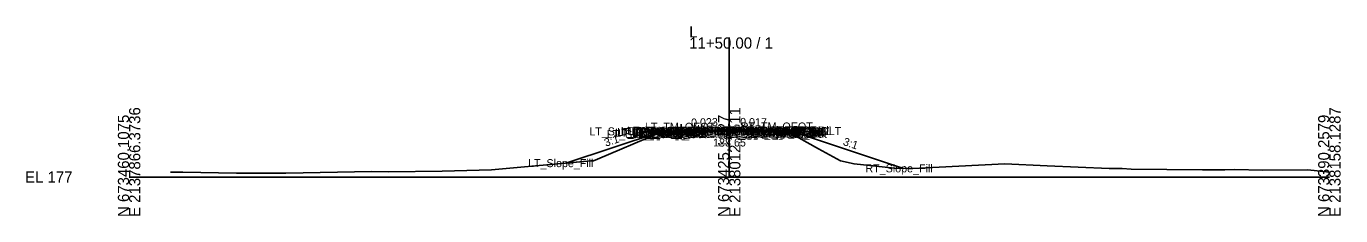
# Model space of a CAD drawing. Extents: x -26 to 5503, y -10 to 7033.
# Drawn here: x -25.7 to 302.8, y 2490.3 to 2537.8 of the extents above; entities that cross this region are included whole.
import ezdxf

# ---------------------------------------------------------------- set-up
doc = ezdxf.new("R2010")
doc.units = 0
for name, color, linetype in [('Default', 7, 'Continuous'), ('Exist CMT Pavement', 7, 'Continuous'), ('Exist Cross Section Cell', 7, 'Continuous'), ('Exist XS Center Line Elevation Label', 7, 'Continuous'), ('Exist XS Ground Line', 7, 'Continuous'), ('Prop CMT Pvmt Course 1', 7, 'Continuous'), ('Prop CMT Pvmt Course 1 Wedge', 7, 'Continuous'), ('Prop CMT Pvmt Course 2', 7, 'Continuous'), ('Prop CMT Pvmt Course 2 Wedge', 7, 'Continuous'), ('Prop CMT Pvmt Course 3', 7, 'Continuous'), ('Prop CMT Pvmt Course 3 Wedge', 7, 'Continuous'), ('Prop CMT Pvmt Surface', 7, 'Continuous'), ('Prop CMT Pvmt Surface Shoulder', 7, 'Continuous'), ('Prop CMT Pvmt Wedge Surface 1', 7, 'Continuous'), ('Prop CMT Pvmt Wedge Surface 2', 7, 'Continuous'), ('Prop CMT Pvmt Wedge Surface 3', 7, 'Continuous'), ('Prop CMT Shld Paved Course 1', 7, 'Continuous'), ('Prop CMT Shld Paved Course 2', 7, 'Continuous'), ('Prop CMT Shld Paved Course 3', 7, 'Continuous'), ('Prop CMT Slope Grass', 7, 'Continuous'), ('Prop CMT Subgrade Earthwork', 7, 'Continuous'), ('Prop XS Earthwork Shape', 7, 'Continuous'), ('Prop XS EOT Tick Mark', 7, 'Continuous'), ('Prop XS SE Text', 7, 'Continuous'), ('Prop XS Side Slope Text', 7, 'Continuous'), ('Prop XS Wedging', 7, 'Continuous')]:
    doc.layers.add(name, color=color, linetype=linetype)

msp = doc.modelspace()

# ---------------------------------------------------------------- linework, layer by layer
at = {"layer": 'Exist CMT Pavement'}
for points in [[(150, 2511.65), (148.67, 2511.63), (144, 2511.57), (139.33, 2511.51), (138, 2511.48)], [(150, 2511.65), (151.32, 2511.63), (155.94, 2511.52), (160.55, 2511.4), (161.87, 2511.36)]]:
    msp.add_lwpolyline(points, dxfattribs=at)
at = {"layer": 'Exist Cross Section Cell'}
for p, q in [((150, 2500), (150, 2534.96)), ((0, 2500), (150, 2500)), ((150, 2500), (300, 2500))]:
    msp.add_line(p, q, dxfattribs=at)
at = {"layer": 'Exist XS Ground Line'}
for p, q in [((117.07, 2504.49), (131.96, 2510.78)), ((131.96, 2510.78), (134.68, 2511.04)), ((134.68, 2511.04), (137.79, 2511.48)), ((137.79, 2511.48), (141.28, 2511.54)), ((141.28, 2511.54), (150.19, 2511.65)), ((150.19, 2511.65), (153.64, 2511.58)), ((153.64, 2511.58), (161.85, 2511.36)), ((161.85, 2511.36), (163.29, 2511.22)), ((163.29, 2511.22), (165.34, 2511.03)), ((165.34, 2511.03), (172.31, 2507.1)), ((172.31, 2507.1), (177.84, 2504.04)), ((90.58, 2501.84), (115.38, 2504.02)), ((115.38, 2504.02), (116.06, 2504.06)), ((116.06, 2504.06), (117.07, 2504.49)), ((177.84, 2504.04), (181.23, 2503.29)), ((10.32, 2501.22), (13.46, 2501.23)), ((13.46, 2501.23), (26.87, 2501.01)), ((26.87, 2501.01), (39.17, 2500.97)), ((39.17, 2500.97), (60.67, 2501.35)), ((60.67, 2501.35), (64.88, 2501.33)), ((64.88, 2501.33), (78.25, 2501.5)), ((78.25, 2501.5), (90.58, 2501.84)), ((181.23, 2503.29), (191.32, 2502.24)), ((191.32, 2502.24), (195.86, 2502.11)), ((195.86, 2502.11), (218.89, 2503.34)), ((218.89, 2503.34), (229.46, 2502.81)), ((229.46, 2502.81), (245, 2502.15)), ((245, 2502.15), (246.8, 2502.16)), ((246.8, 2502.16), (248.2, 2502.14)), ((248.2, 2502.14), (250.48, 2502)), ((250.48, 2502), (268.33, 2501.81)), ((268.33, 2501.81), (270.6, 2501.8)), ((270.6, 2501.8), (272.18, 2501.81)), ((272.18, 2501.81), (273.91, 2501.82)), ((273.91, 2501.82), (276.4, 2501.85)), ((276.4, 2501.85), (283.27, 2501.76)), ((283.27, 2501.76), (294.6, 2501.77)), ((294.6, 2501.77), (300, 2501.24))]:
    msp.add_line(p, q, dxfattribs=at)
at = {"layer": 'Prop CMT Pvmt Course 1'}
for points in [[(150, 2511.87), (138, 2511.59)], [(138, 2511.47), (150, 2511.74)], [(138, 2511.59), (138, 2511.34), (138, 2511.34), (138, 2511.47)], [(150, 2511.74), (150, 2511.87)], [(150, 2511.87), (162, 2511.66)], [(150, 2511.74), (150, 2511.87)], [(161.87, 2511.53), (150, 2511.74)], [(161.87, 2511.41), (161.87, 2511.53)], [(162, 2511.41), (161.87, 2511.41)], [(162, 2511.66), (162, 2511.41)]]:
    msp.add_lwpolyline(points, dxfattribs=at)
at = {"layer": 'Prop CMT Pvmt Course 1 Wedge'}
for points in [[(150, 2511.74), (138, 2511.47)], [(150, 2511.74), (161.87, 2511.53)]]:
    msp.add_lwpolyline(points, dxfattribs=at)
at = {"layer": 'Prop CMT Pvmt Course 2'}
for points in [[(161.87, 2511.2), (161.87, 2511.41)], [(161.87, 2511.41), (162, 2511.41)], [(162, 2511.2), (161.87, 2511.2)], [(162, 2511.41), (162, 2511.2)]]:
    msp.add_lwpolyline(points, dxfattribs=at)
at = {"layer": 'Prop CMT Pvmt Course 2 Wedge'}
for points in [[(150, 2511.62), (138, 2511.34)], [(150, 2511.62), (161.87, 2511.41)]]:
    msp.add_lwpolyline(points, dxfattribs=at)
at = {"layer": 'Prop CMT Pvmt Course 3'}
for points in [[(138, 2511.14), (138, 2511.14), (138, 2510.8), (138, 2510.8)], [(138, 2510.8), (138, 2511.14)], [(161.87, 2511.2), (162, 2511.2)], [(161.87, 2510.87), (161.87, 2511.2)], [(162, 2510.87), (161.87, 2510.87)], [(162, 2511.2), (162, 2510.87)]]:
    msp.add_lwpolyline(points, dxfattribs=at)
at = {"layer": 'Prop CMT Pvmt Course 3 Wedge'}
for points in [[(150, 2511.41), (138, 2511.14)], [(150, 2511.41), (161.87, 2511.2)]]:
    msp.add_lwpolyline(points, dxfattribs=at)
at = {"layer": 'Prop CMT Pvmt Surface'}
for points in [[(150, 2511.87), (138, 2511.59)], [(150, 2511.87), (162, 2511.66)]]:
    msp.add_lwpolyline(points, dxfattribs=at)
at = {"layer": 'Prop CMT Pvmt Surface Shoulder'}
for points in [[(138, 2511.59), (135.96, 2511.55)], [(162, 2511.66), (164.02, 2511.62)]]:
    msp.add_lwpolyline(points, dxfattribs=at)
at = {"layer": 'Prop CMT Pvmt Wedge Surface 1'}
for points in [[(150, 2511.74), (138, 2511.47)], [(138, 2511.47), (138, 2511.59)], [(138, 2511.59), (138, 2511.59)], [(150, 2511.74), (161.87, 2511.53)], [(161.87, 2511.53), (161.87, 2511.66)], [(161.87, 2511.66), (162, 2511.66)]]:
    msp.add_lwpolyline(points, dxfattribs=at)
at = {"layer": 'Prop CMT Pvmt Wedge Surface 2'}
for points in [[(150, 2511.62), (138, 2511.34)], [(138, 2511.34), (138, 2511.59)], [(138, 2511.34), (138, 2511.34)], [(150, 2511.62), (161.87, 2511.41), (162, 2511.41)], [(162, 2511.41), (162, 2511.66)]]:
    msp.add_lwpolyline(points, dxfattribs=at)
at = {"layer": 'Prop CMT Pvmt Wedge Surface 3'}
for points in [[(138, 2511.14), (138, 2511.59)], [(150, 2511.41), (138, 2511.14)], [(138, 2511.14), (138, 2511.14)], [(150, 2511.41), (161.87, 2511.2), (162, 2511.2)], [(162, 2511.2), (162, 2511.66)]]:
    msp.add_lwpolyline(points, dxfattribs=at)
at = {"layer": 'Prop CMT Shld Paved Course 1'}
for points in [[(138, 2511.59), (135.96, 2511.55), (135.71, 2511.29)], [(135.71, 2511.29), (138, 2511.34)], [(138, 2511.34), (138, 2511.59)], [(162, 2511.66), (164.02, 2511.62), (164.28, 2511.37)], [(162, 2511.41), (162, 2511.66)], [(164.28, 2511.37), (162, 2511.41)]]:
    msp.add_lwpolyline(points, dxfattribs=at)
at = {"layer": 'Prop CMT Shld Paved Course 2'}
for points in [[(138, 2511.34), (135.71, 2511.29), (135.49, 2511.08)], [(135.49, 2511.08), (138, 2511.14)], [(138, 2511.14), (138, 2511.34)], [(162, 2511.41), (164.28, 2511.37), (164.49, 2511.16)], [(162, 2511.2), (162, 2511.41)], [(164.49, 2511.16), (162, 2511.2)]]:
    msp.add_lwpolyline(points, dxfattribs=at)
at = {"layer": 'Prop CMT Shld Paved Course 3'}
for points in [[(135.49, 2511.08), (135.15, 2510.74)], [(135.15, 2510.74), (138, 2510.8)], [(138, 2511.14), (135.49, 2511.08)], [(135.49, 2511.08), (135.49, 2511.08)], [(138, 2510.8), (138, 2511.14)], [(162, 2511.2), (164.49, 2511.16)], [(162, 2510.87), (162, 2511.2)], [(164.83, 2510.82), (162, 2510.87)], [(164.49, 2511.16), (164.49, 2511.16)], [(164.49, 2511.16), (164.83, 2510.82)]]:
    msp.add_lwpolyline(points, dxfattribs=at)
at = {"layer": 'Prop CMT Slope Grass'}
for points in [[(132.6, 2511.28), (109.2, 2503.48)], [(135.96, 2511.55), (132.6, 2511.28)], [(164.02, 2511.62), (165.6, 2511.5)], [(165.6, 2511.5), (193.57, 2502.18)]]:
    msp.add_lwpolyline(points, dxfattribs=at)
at = {"layer": 'Prop CMT Subgrade Earthwork'}
for points in [[(135.15, 2510.74), (134.46, 2511.43)], [(138, 2510.8), (135.15, 2510.74)], [(138, 2510.8), (138, 2511.48)], [(138, 2510.8), (138, 2510.8)], [(161.87, 2510.87), (161.87, 2511.36)], [(161.87, 2510.87), (162, 2510.87)], [(162, 2510.87), (164.83, 2510.82)], [(164.83, 2510.82), (165.52, 2511.51)]]:
    msp.add_lwpolyline(points, dxfattribs=at)
at = {"layer": 'Prop XS Earthwork Shape'}
for points in [[(132.6, 2511.28), (109.2, 2503.48), (115.38, 2504.02), (116.06, 2504.06), (117.07, 2504.49), (131.96, 2510.78), (134.68, 2511.04), (134.83, 2511.06), (134.46, 2511.43)], [(138, 2510.8), (135.15, 2510.74), (134.83, 2511.06), (137.79, 2511.48), (138, 2511.48)], [(141.28, 2511.54), (144, 2511.57), (139.33, 2511.51)], [(150.19, 2511.65), (151.32, 2511.63), (150, 2511.65)], [(153.64, 2511.58), (155.94, 2511.52), (151.32, 2511.63)], [(161.87, 2510.87), (161.87, 2511.36), (163.29, 2511.22), (165.06, 2511.05), (164.83, 2510.82), (162, 2510.87)], [(165.6, 2511.5), (193.57, 2502.18), (191.32, 2502.24), (181.23, 2503.29), (177.84, 2504.04), (172.31, 2507.1), (165.34, 2511.03), (165.06, 2511.05), (165.52, 2511.51)]]:
    msp.add_lwpolyline(points, close=True, dxfattribs=at)
at = {"layer": 'Prop XS EOT Tick Mark'}
for points in [[(138, 2511.59), (138, 2512.59)], [(138, 2511.59), (138, 2512.59)], [(162, 2511.66), (162, 2512.66)], [(162, 2511.66), (162, 2512.66)]]:
    msp.add_lwpolyline(points, dxfattribs=at)
at = {"layer": 'Prop XS Wedging'}
for p, q in [((138, 2513.27), (138, 2509.47)), ((162, 2512.7), (162, 2509.38))]:
    msp.add_line(p, q, dxfattribs=at)

# ---------------------------------------------------------------- texts
at = {"layer": 'Default'}
for s, height, p in [('LT_TM_OEOT', 2, (128.94, 2511.59)), ('RT_TM_OEOT', 2, (152.9, 2511.66)), ('LT_Sub_Trench_Out_DLT', 2, (115.03, 2510.43)), ('LT_Sub_Trench_Out', 2, (119.36, 2509.74)), ('LT_PS3_Shelf_Out', 2, (121.48, 2510.08)), ('LT_GS_OS_CTL', 2, (121.97, 2510.28)), ('LT_PV_Sub_Tie_Out', 2, (122.95, 2510.48)), ('LT_PV1_OEEOP_Null', 2, (124.46, 2510.59)), ('LT_PV_EG_TestPt3', 2, (124.85, 2510.51)), ('LT_PV_OEEOP_EG', 2, (125.54, 2510.48)), ('LT_PS3_OEOP', 2, (125.73, 2510.08)), ('LT_PS2_OEOP', 2, (125.94, 2510.29)), ('LT_PV1_OEEOP_W', 2, (125.98, 2510.47)), ('LT_PS1_OEOP', 2, (126.76, 2510.55)), ('LT_Sub_OEEOP', 2, (127.21, 2509.8)), ('LT_PV2_OEEOP', 2, (127.31, 2510.34)), ('LT_PV3_OEEOP', 2, (127.31, 2510.14)), ('LT_Sub_OEOT', 2, (128.08, 2509.8)), ('LT_PV2_OEOT', 2, (128.17, 2510.34)), ('LT_PV3_OEOT', 2, (128.17, 2510.14)), ('LT_PV1_OEOT', 2, (128.74, 2510.59)), ('LT_PV_EG_TestPt2', 2, (129.51, 2510.57)), ('LT_PV_EG_TestPt1', 2, (134.75, 2510.63)), ('RT_PV_EG_TestPt1', 2, (137.35, 2510.63)), ('PV_EPGL_EG', 2, (141.24, 2510.65)), ('RT_PV_EG_TestPt2', 2, (141.4, 2510.52)), ('PV2_PGL_W', 2, (142.02, 2510.62)), ('PV3_PGL_W', 2, (142.02, 2510.41)), ('PV1_PGL_W', 2, (142.58, 2510.74)), ('PV1_PGL', 2, (144.47, 2510.87)), ('RT_PV_EG_TestPt3', 2, (146.02, 2510.4)), ('RT_Sub_Trench_Out_DLT', 2, (146.04, 2510.51)), ('RT_PV_Sub_Tie_Out', 2, (146.77, 2510.36)), ('RT_PV1_OEEOP_Null', 2, (148.28, 2510.66)), ('RT_Sub_Trench_Out', 2, (148.99, 2509.82)), ('RT_PV_OEEOP_EG', 2, (149.37, 2510.36)), ('RT_PV1_OEEOP_W', 2, (149.81, 2510.53)), ('RT_PS3_Shelf_Out', 2, (150.43, 2510.16)), ('RT_Sub_OEEOP', 2, (151.04, 2509.87)), ('RT_PV2_OEEOP', 2, (151.13, 2510.41)), ('RT_PV3_OEEOP', 2, (151.13, 2510.2)), ('RT_Sub_OEOT', 2, (152.03, 2509.87)), ('RT_PV2_OEOT', 2, (152.13, 2510.41)), ('RT_PV3_OEOT', 2, (152.13, 2510.2)), ('RT_PV1_OEOT', 2, (152.69, 2510.66)), ('RT_PS2_OEOP', 2, (154.47, 2510.37)), ('RT_PS3_OEOP', 2, (154.68, 2510.16)), ('RT_PS1_OEOP', 2, (154.78, 2510.62)), ('RT_GS_OS_CTL', 2, (154.92, 2510.5)), ('LT_Slope_Fill', 2, (99.72, 2502.48)), ('RT_Slope_Fill', 2, (184.05, 2501.18)), ('-', 0.0001, (0, 2500))]:
    msp.add_text(s, height=height, dxfattribs=at).set_placement(p)
at = {"layer": 'Exist Cross Section Cell'}
for s, p in [('L', (140, 2534.96)), ('11+50.00 / 1', (140, 2532.16)), ('EL 177', (-26, 2498.6))]:
    msp.add_text(s, height=2.8, dxfattribs=at).set_placement(p)
for s, p in [('E 2137866.3736', (2.8, 2490)), ('E 2138012.2511', (152.8, 2490)), ('E 2138158.1287', (302.8, 2490)), ('N 673460.1075', (0, 2490)), ('N 673425.1827', (150, 2490)), ('N 673390.2579', (300, 2490))]:
    msp.add_text(s, height=2.8, rotation=90, dxfattribs=at).set_placement(p)
at = {"layer": 'Exist XS Center Line Elevation Label'}
msp.add_text('188.65', height=2, dxfattribs=at).set_placement((145.98, 2507.65))
at = {"layer": 'Prop XS SE Text'}
for s, rotation, p in [('0.023', 1.2976, (140.49, 2512.65)), ('0.017', 358.9998, (152.7, 2512.82))]:
    msp.add_text(s, height=2, rotation=rotation, dxfattribs=at).set_placement(p)
at = {"layer": 'Prop XS Side Slope Text'}
for rotation, p in [(18.4349, (119.14, 2507.58)), (341.5651, (178.3, 2508.06))]:
    msp.add_text('3:1', height=2, rotation=rotation, dxfattribs=at).set_placement(p)

doc.saveas('drawing.dxf')
